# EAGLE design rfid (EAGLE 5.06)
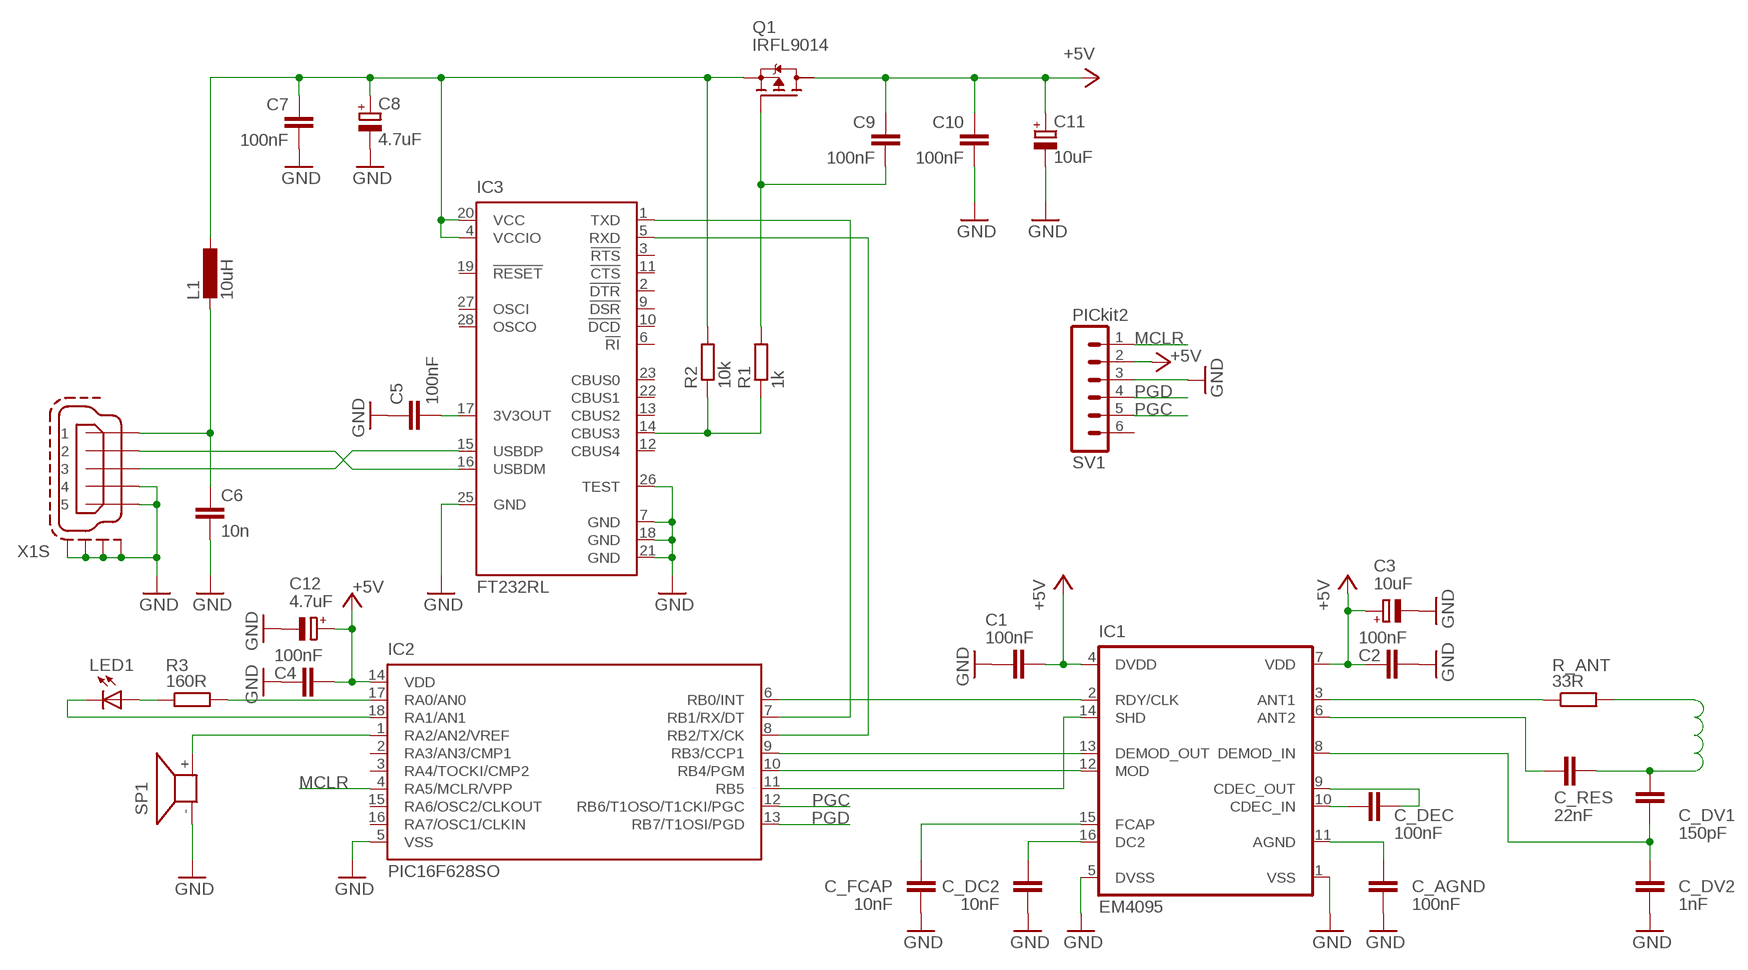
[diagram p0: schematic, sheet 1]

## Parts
C1  100nF  C-EUC1206  [C1206]
C2  100nF  C-EUC1206  [C1206]
C3  10uF  CPOL-EUB/3528-21R  [B/3528-21R]
C4  100nF  C-EUC1206  [C1206]
C5  100nF  C-EUC1206  [C1206]
C6  10n  C-EUC1206  [C1206]
C7  100nF  C-EUC1206  [C1206]
C8  4.7uF  CPOL-EUB/3528-21R  [B/3528-21R]
C9  100nF  C-EUC1206  [C1206]
C10  100nF  C-EUC1206  [C1206]
C11  10uF  CPOL-EUB/3528-21R  [B/3528-21R]
C12  4.7uF  CPOL-EUB/3528-21R  [B/3528-21R]
C_AGND  100nF  C-EUC1206  [C1206]
C_DC2  10nF  C-EUC1206  [C1206]
C_DEC  100nF  C-EUC1206  [C1206]
C_DV1  150pF  C-EUC1206  [C1206]
C_DV2  1nF  C-EUC1206  [C1206]
C_FCAP  10nF  C-EUC1206  [C1206]
C_RES  22nF  C-EUC1206  [C1206]
IC1  EM4095  [SO16]
IC2  PIC16F628SO  [SO-18W]
IC3  FT232RL  [SSOP28]
L1  10uH  L-EU0207/10  [0207/10]
LED1  LED5MM  [LED5MM]
Q1  IRFL9014  BSP170P  [SOT223]
R1  1k  R-EU_R1206  [R1206]
R2  10k  R-EU_R1206  [R1206]
R3  160R  R-EU_R1206  [R1206]
R_ANT  33R  R-EU_R1206  [R1206]
SP1  AL11P  [AL11P]
SV1  PICkit2  MA06-1  [MA06-1]
X1  MINI-USB-SCHIELD-32005-201  [32005-201]

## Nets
5V_VCC: C7.1 C8.+ IC3.4(VCCIO) IC3.20(VCC) L1.1 Q1.3(S) R2.2
+5V: C1.2 C2.1 C3.+ C4.2 C9.1 C10.1 C11.+ C12.+ IC1.4(DVDD) IC1.7(VDD) IC2.14(VDD) Q1.4(D1) SV1.2
AGND: C_AGND.1 IC1.11(AGND)
ANTENA: C_DV1.1 C_RES.1 R_ANT.2
GND: C1.1 C2.2 C3.- C4.1 C5.1 C6.2 C7.2 C8.- C10.2 C11.- C12.- C_AGND.2 C_DC2.2 C_DV2.2 C_FCAP.2 IC1.1(VSS) IC1.5(DVSS) IC2.5(VSS) IC3.7(GND) IC3.18(GND) IC3.21(GND) IC3.25(GND) IC3.26(TEST) SP1.- SV1.3 X1.4 X1.5 X1.M1(S:S1) X1.M2(S:S2) X1.M3(S:S3) X1.M4(S:S4)
MCLR: IC2.4(RA5/MCLR/VPP) SV1.1
N$1: C_DEC.2 IC1.10(CDEC_IN)
N$2: C_DEC.1 IC1.9(CDEC_OUT)
N$3: C_RES.2 IC1.6(ANT2)
N$4: C_DV1.2 C_DV2.1 IC1.8(DEMOD_IN)
N$5: IC1.3(ANT1) R_ANT.1
N$6: C_DC2.1 IC1.16(DC2)
N$7: C_FCAP.1 IC1.15(FCAP)
N$9: IC1.13(DEMOD_OUT) IC2.9(RB3/CCP1)
N$10: IC1.2(RDY/CLK) IC2.6(RB0/INT)
N$11: IC1.12(MOD) IC2.10(RB4/PGM)
N$12: IC1.14(SHD) IC2.11(RB5)
N$13: IC2.8(RB2/TX/CK) IC3.5(RXD)
N$14: IC2.7(RB1/RX/DT) IC3.1(TXD)
N$15: C5.2 IC3.17(3V3OUT)
N$16: IC3.16(USBDM) X1.2
N$17: IC3.15(USBDP) X1.3
N$18: C6.1 L1.2 X1.1
N$19: LED1.A R3.1
N$20: IC3.14(CBUS3) R1.1 R2.1
N$21: C9.2 Q1.1(G) R1.2
N$22: IC2.17(RA0/AN0) R3.2
N$23: IC2.18(RA1/AN1) LED1.K(C)
N$24: IC2.1(RA2/AN2/VREF) SP1.+
PGC: IC2.12(RB6/T1OSO/T1CKI/PGC) SV1.5
PGD: IC2.13(RB7/T1OSI/PGD) SV1.4
Unconnected: IC2.2(RA3/AN3/CMP1) IC2.3(RA4/TOCKI/CMP2) IC2.15(RA6/OSC2/CLKOUT) IC2.16(RA7/OSC1/CLKIN) IC3.2(!DTR) IC3.3(!RTS) IC3.6(!RI) IC3.9(!DSR) IC3.10(!DCD) IC3.11(!CTS) IC3.12(CBUS4) IC3.13(CBUS2) IC3.19(!RESET) IC3.22(CBUS1) IC3.23(CBUS0) IC3.27(OSCI) IC3.28(OSCO) Q1.2(D) SV1.6

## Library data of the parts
C1 C2 C4-C7 C9 C10 C_AGND C_DC2 C_DEC C_DV1 C_DV2 C_FCAP C_RES = rcl:C-EU: CAPACITOR, European symbol
C3 C8 C11 C12 = rcl:CPOL-EU: POLARIZED CAPACITOR, European symbol
IC1 = EM Microelectronic:EM4095: Read/Write analog front end for 125kHz RFID Basestation
IC2 = microchip:PIC16F62*: FLASH-Based 8-Bit CMOS Microcontroller Source: http://ww1.microchip.com/downloads/en/DeviceDoc/40300C.pdf
IC3 = ftdichip:FT232R: Source: http://www.ftdichip.com/Documents/DataSheets/DS_FT232R_v104.pdf
L1 = rcl:L-EU: INDUCTOR, European symbol
LED1 = led:LED: LED
Q1 = transistor-fet:BSP170P: SIPMOS(R) Small-Signal-Transistor P-Channel, Enhancement mode Source: http://www.infineon.com/upload/Document/BSP170P_Rev2.4.pdf
R1-R3 R_ANT = rcl:R-EU_: RESISTOR, European symbol
SP1 = buzzer:AL11P: SPEAKER
SV1 = con-lstb:MA06-1: PIN HEADER
X1 = con-cypressindustries:MINI-USB-SCHIELD-: MINI USB-B Conector Source: www.cypressindustries.com

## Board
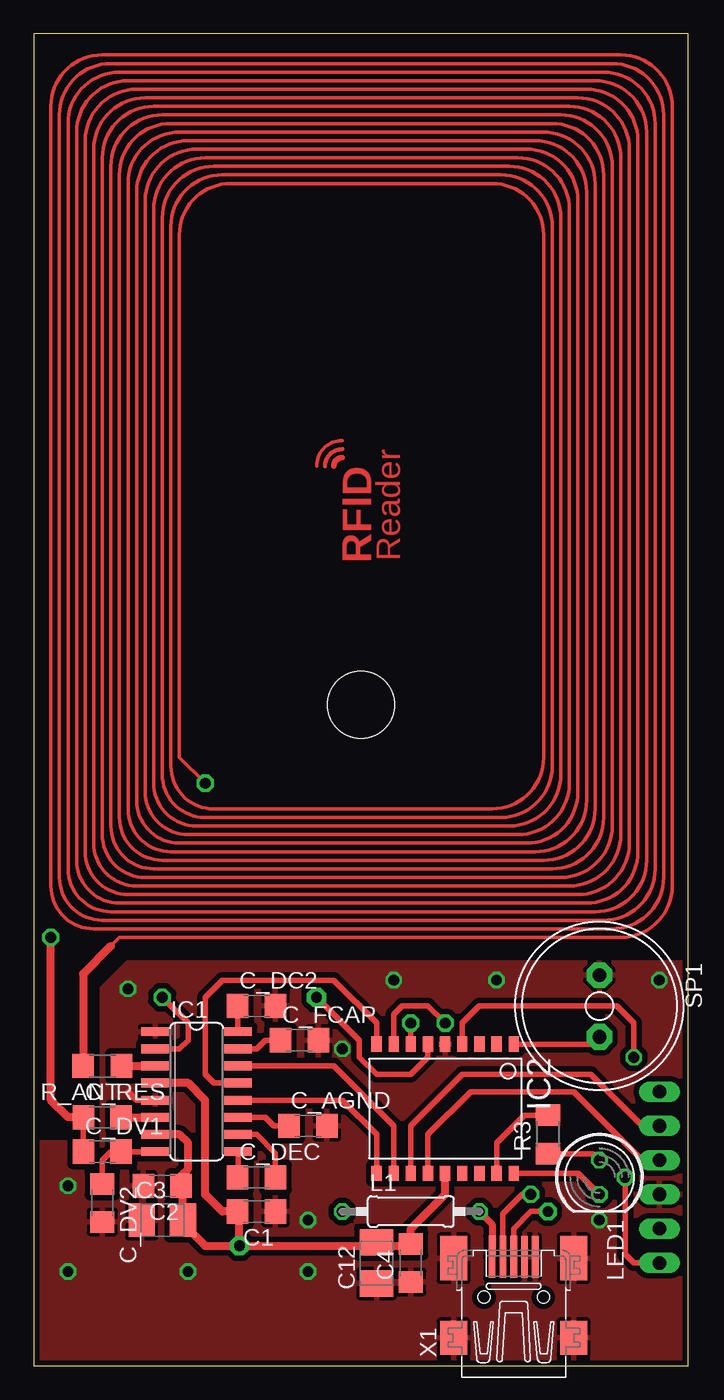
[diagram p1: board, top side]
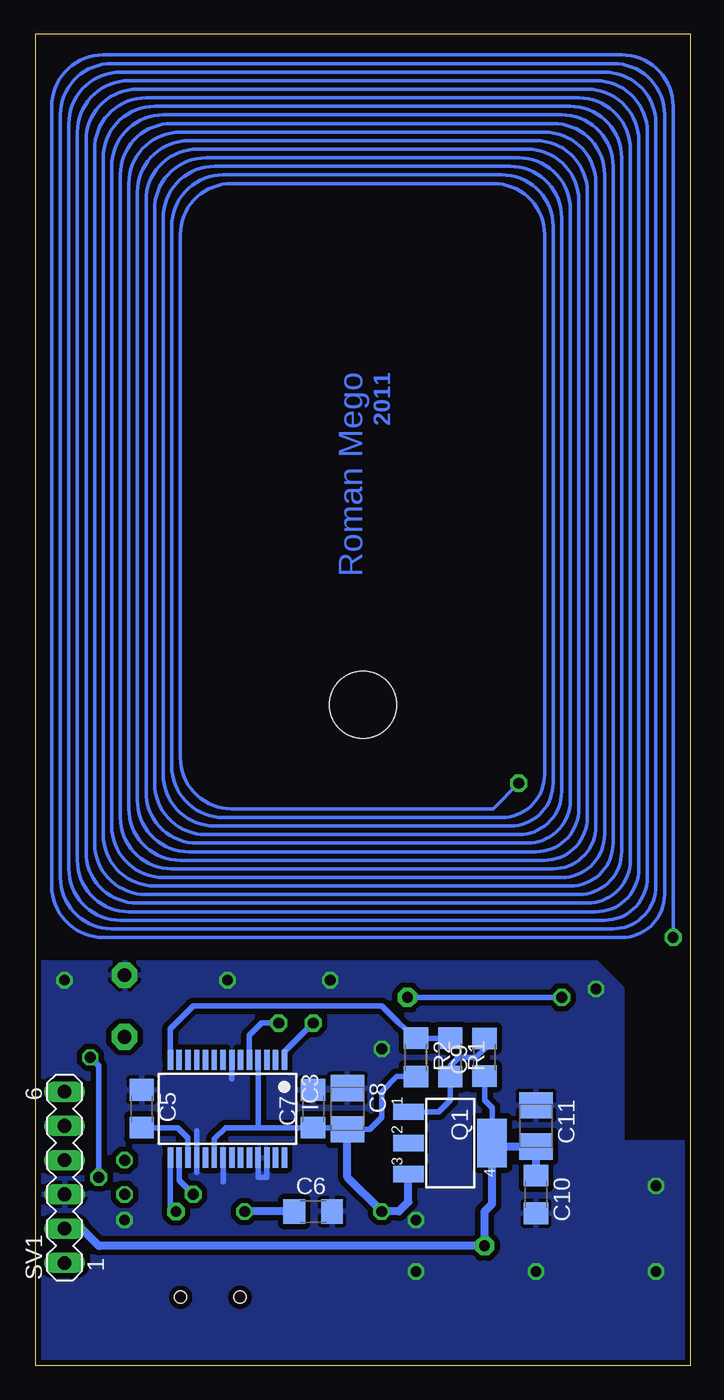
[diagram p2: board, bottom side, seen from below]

Size 48.5 x 98.73 mm. Coordinates in mm from the lower left corner, seen from the top.
Outline: 0,0 48.5,0 48.5,98.73 0,98.73 0,0
Copper layers (1*16): Top 0.0356mm / dielectric 1.5011mm / Bottom 0.0356mm
Design rules "LaenPCBOrder *": minimum track width 0.2mm, minimum drill 0.4mm, track to track 0.2mm, track to pad 0.2mm, pad to pad 0.2mm, via to via 0.2mm, smd to smd 0.2mm, copper to edge 0.4mm, drill to drill 6mil, minimum pad ring 7mil, minimum via ring 7mil, stop-mask expansion 4mil, vias tented up to drill 0mil, thermal gap 10mil
Holes 5 mm at 24.25,49

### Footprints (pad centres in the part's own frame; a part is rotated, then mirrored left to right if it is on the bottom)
C1206 = smd 1.6 x 1.8: 1 -1.4,0; 2 1.4,0
B/3528-21R = smd 1.95 x 2.5: + 1.525,0; - -1.525,0
SO16 = smd 0.66 x 2.032: 1 -4.445,-3.073; 2 -3.175,-3.073; 3 -1.905,-3.073; 4 -0.635,-3.073; 5 0.635,-3.073; 6 1.905,-3.073; 7 3.175,-3.073; 8 4.445,-3.073; 9 4.445,3.073; 10 3.175,3.073; 11 1.905,3.073; 12 0.635,3.073; 13 -0.635,3.073; 14 -1.905,3.073; 15 -3.175,3.073; 16 -4.445,3.073
SO-18W = smd 0.762 x 1.143: 1 -5.08,-4.788; 2 -3.81,-4.788; 3 -2.54,-4.788; 4 -1.27,-4.788; 5 0,-4.788; 6 1.27,-4.788; 7 2.54,-4.788; 8 3.81,-4.788; 9 5.08,-4.788; 10 5.08,4.788; 11 3.81,4.788; 12 2.54,4.788; 13 1.27,4.788; 14 0,4.788; 15 -1.27,4.788; 16 -2.54,4.788; 17 -3.81,4.788; 18 -5.08,4.788
SSOP28 = smd 0.4 x 1.5: 1 -4.225,-3.625; 2 -3.575,-3.625; 3 -2.925,-3.625; 4 -2.275,-3.625; 5 -1.625,-3.625; 6 -0.975,-3.625; 7 -0.325,-3.625; 8 0.325,-3.625; 9 0.975,-3.625; 10 1.625,-3.625; 11 2.275,-3.625; 12 2.925,-3.625; 13 3.575,-3.625; 14 4.225,-3.625; 15 4.225,3.625; 16 3.575,3.625; 17 2.925,3.625; 18 2.275,3.625; 19 1.625,3.625; 20 0.975,3.625; 21 0.325,3.625; 22 -0.325,3.625; 23 -0.975,3.625; 24 -1.625,3.625; 25 -2.275,3.625; 26 -2.925,3.625; 27 -3.575,3.625; 28 -4.225,3.625
0207/10 = drill 0.813 octagon: 1 -5.08,0; 2 5.08,0
LED5MM = drill 0.813 octagon: A -1.27,0; K 1.27,0
SOT223 = smd 1.219 x 2.235: 1 -2.311,-3.099; 2 0,-3.099; 3 2.311,-3.099 | smd 3.6 x 2.2: 4 0,3.099
R1206 = smd 1.6 x 1.803: 1 -1.422,0; 2 1.422,0
AL11P = drill 1.016 pad 1.905 octagon: + 2.286,0; - -2.286,0
MA06-1 = drill 1.016 long: 1 -6.35,0; 2 -3.81,0; 3 -1.27,0; 4 1.27,0; 5 3.81,0; 6 6.35,0
32005-201 = smd 3.1 x 0.5: 1 3,1.6; 2 3,0.8; 3 3,0; 4 3,-0.8; 5 3,-1.6 | smd 2.5 x 2: M1 -3,-4.45; M2 -3,4.45 | smd 3.3 x 2: M3 2.9,4.45; M4 2.9,-4.45 | hole 0.9: 0,2.2; 0,-2.2

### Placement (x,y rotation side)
C1  16.51,11.43 180 top
C2  9.53,13.34 180 top
C3  9.53,10.79 0 top
C4  27.94,7.62 90 top
C5  40.64,19.05 270 bottom
C6  27.94,11.43 0 bottom
C7  27.94,19.05 90 bottom
C8  25.4,19.05 270 bottom
C9  15.24,22.86 90 bottom
C10  11.43,12.7 270 bottom
C11  11.43,17.78 270 bottom
C12  25.4,7.62 90 top
C_AGND  20.32,17.78 0 top
C_DC2  16.51,26.67 0 top
C_DEC  16.51,13.97 0 top
C_DV1  5.08,15.88 0 top
C_DV2  5.08,12.06 270 top
C_FCAP  19.68,24.13 0 top
C_RES  5.08,18.41 0 top
IC1  12.06,20.32 270 top
IC2  30.48,19.05 180 top
IC3  34.29,19.05 180 bottom
L1  27.94,11.43 0 top
LED1  41.91,13.97 270 top
Q1  17.78,16.51 270 bottom
R1  17.78,22.86 270 bottom
R2  20.32,22.86 270 bottom
R3  38.1,17.14 90 top
R_ANT  5.08,22.23 180 top
SP1  41.91,26.67 270 top
SV1  46.35,13.97 90 bottom
X1  35.56,5.08 90 top

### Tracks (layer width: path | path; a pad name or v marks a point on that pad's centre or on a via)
5V_VCC
  Bottom 0.406: 32.02,17.65 C7.1 25.52,17.65 C8.+ 23.75,17.52 22.86,18.41 22.86,20.32 21.74,21.44 R2.2 | 32.02,17.65 IC3.4 | IC3.20 35.27,16.8 34.42,17.65 32.02,17.65
  Bottom 0.61: Q1.3 20.88,12.14 21.59,11.43 L1.1 25.4,13.97 C8.+
+5V  (via drill 0.8 pad 1.42)
  Top 0.61: IC1.4 11.43,20.95 12.7,19.68 12.7,12.7 13.97,11.43 C1.2 15.24,11.3 v15.24,8.89 | IC1.7 10.79,17.14 11.43,16.51 11.43,14.61 10.93,14.1 C2.1 11.05,13.21 C3.+ 11.05,10.54 12.7,8.89 v15.24,8.89 | IC2.14 30.48,12.7 27.94,10.16 C4.2 27.81,8.89 25.4,8.89 | v15.24,8.89 25.4,8.89 | 25.4,8.89 C12.+
  Bottom 0.406: Q1.4 14.68,19.13 15.24,19.68 C9.1
  Bottom 0.61: C10.1 C11.+ 14.43,16.25 Q1.4 14.68,11.99 15.24,11.43 v15.24,8.89 43.81,8.89 45.09,10.16 SV1.2
AGND
  Top 0.406: IC1.11 17.14,18.41 17.78,17.78 C_AGND.1
ANTENA  (via drill 0.8 pad 1.27)
  Top 0.254: 5.71,31.11 6.35,31.75 43.5,31.75 arc90 47.31,35.56 47.31,93.34 arc90 43.5,97.16 5.08,97.16 arc90 1.27,93.34 1.27,35.56 arc90 4.45,32.38 42.86,32.38 arc90 46.67,36.2 46.67,92.71 arc90 42.86,96.52 5.71,96.52 arc90 1.91,92.71 1.91,36.2 arc90 5.08,33.02 42.23,33.02 arc90 46.04,36.83 46.04,92.08 arc90 42.23,95.89 6.35,95.89 arc90 2.54,92.08 2.54,36.83 arc90 5.71,33.66 41.59,33.66 arc90 45.4,37.47 45.4,91.44 arc90 41.59,95.25 6.99,95.25 arc90 3.17,91.44 3.17,37.47 arc90 6.35,34.29 40.96,34.29 arc90 44.77,38.1 44.77,90.81 arc90 40.96,94.61 7.62,94.61 arc90 3.81,90.81 3.81,38.1 arc90 6.99,34.92 40.32,34.92 arc90 44.13,38.73 44.13,90.17 arc90 40.32,93.98 8.26,93.98 arc90 4.45,90.17 4.45,38.73 arc90 7.62,35.56 39.69,35.56 arc90 43.5,39.37 43.5,89.53 arc90 39.69,93.34 8.89,93.34 arc90 5.08,89.53 5.08,39.37 arc90 8.26,36.2 39.05,36.2 arc90 42.86,40.01 42.86,88.9 arc90 39.05,92.71 9.53,92.71 arc90 5.71,88.9 5.71,40.01 arc90 8.89,36.83 38.42,36.83 arc90 42.23,40.64 42.23,88.27 arc90 38.42,92.08 10.16,92.08 arc90 6.35,88.27 6.35,40.64 arc90 9.53,37.47 37.78,37.47 arc90 41.59,41.27 41.59,87.63 arc90 37.78,91.44 10.79,91.44 arc90 6.99,87.63 6.99,41.27 arc90 10.16,38.1 37.15,38.1 arc90 40.96,41.91 40.96,87 arc90 37.15,90.81 11.43,90.81 arc90 7.62,87 7.62,41.91 arc90 10.79,38.73 36.51,38.73 arc90 40.32,42.55 40.32,86.36 arc90 36.51,90.17 12.06,90.17 arc90 8.26,86.36 8.26,42.55 arc90 11.43,39.37 35.88,39.37 arc90 39.69,43.18 39.69,85.72 arc90 35.88,89.53 12.7,89.53 arc90 8.89,85.72 8.89,43.18 arc90 12.06,40.01 35.24,40.01 arc90 39.05,43.81 39.05,85.09 arc90 35.24,88.9 13.34,88.9 arc90 9.53,85.09 9.53,43.81 arc90 12.7,40.64 34.61,40.64 arc90 38.42,44.45 38.42,84.45 arc90 34.61,88.27 13.97,88.27 arc90 10.16,84.45 10.16,44.45 arc90 13.34,41.27 33.97,41.27 arc90 37.78,45.09 37.78,83.82 arc90 33.97,87.63 14.61,87.63 arc90 10.79,83.82 10.79,45.09 v12.7,43.18
  Top 0.406: C_DV1.1 C_RES.1
  Top 0.61: R_ANT.2 3.66,29.06 5.71,31.11 | v1.27,31.75 1.27,19.68 2.54,18.41 C_RES.1
  Bottom 0.254: v12.7,43.18 14.61,41.27 33.97,41.27 arc90 37.78,45.09 37.78,83.82 arc90 33.97,87.63 14.61,87.63 arc90 10.79,83.82 10.79,43.81 arc90 13.97,40.64 34.61,40.64 arc90 38.42,44.45 38.42,84.45 arc90 34.61,88.27 13.97,88.27 arc90 10.16,84.45 10.16,43.18 arc90 13.34,40.01 35.24,40.01 arc90 39.05,43.81 39.05,85.09 arc90 35.24,88.9 13.34,88.9 arc90 9.53,85.09 9.53,42.55 arc90 12.7,39.37 35.88,39.37 arc90 39.69,43.18 39.69,85.72 arc90 35.88,89.53 12.7,89.53 arc90 8.89,85.72 8.89,41.91 arc90 12.06,38.73 36.51,38.73 arc90 40.32,42.55 40.32,86.36 arc90 36.51,90.17 12.06,90.17 arc90 8.26,86.36 8.26,41.27 arc90 11.43,38.1 37.15,38.1 arc90 40.96,41.91 40.96,87 arc90 37.15,90.81 11.43,90.81 arc90 7.62,87 7.62,40.64 arc90 10.79,37.47 37.78,37.47 arc90 41.59,41.27 41.59,87.63 arc90 37.78,91.44 10.79,91.44 arc90 6.99,87.63 6.99,40.01 arc90 10.16,36.83 38.42,36.83 arc90 42.23,40.64 42.23,88.27 arc90 38.42,92.08 10.16,92.08 arc90 6.35,88.27 6.35,39.37 arc90 9.53,36.2 39.05,36.2 arc90 42.86,40.01 42.86,88.9 arc90 39.05,92.71 9.53,92.71 arc90 5.71,88.9 5.71,38.73 arc90 8.89,35.56 39.69,35.56 arc90 43.5,39.37 43.5,89.53 arc90 39.69,93.34 8.89,93.34 arc90 5.08,89.53 5.08,38.1 arc90 8.26,34.92 40.32,34.92 arc90 44.13,38.73 44.13,90.17 arc90 40.32,93.98 8.26,93.98 arc90 4.45,90.17 4.45,37.47 arc90 7.62,34.29 40.96,34.29 arc90 44.77,38.1 44.77,90.81 arc90 40.96,94.61 7.62,94.61 arc90 3.81,90.81 3.81,36.83 arc90 6.99,33.66 41.59,33.66 arc90 45.4,37.47 45.4,91.44 arc90 41.59,95.25 6.99,95.25 arc90 3.17,91.44 3.17,36.2 arc90 6.35,33.02 42.23,33.02 arc90 46.04,36.83 46.04,92.08 arc90 42.23,95.89 6.35,95.89 arc90 2.54,92.08 2.54,35.56 arc90 5.71,32.38 42.86,32.38 arc90 46.67,36.2 46.67,92.71 arc90 42.86,96.52 5.71,96.52 arc90 1.91,92.71 1.91,34.92 arc90 5.08,31.75 43.5,31.75 arc90 47.31,35.56 47.31,93.34 arc90 43.5,97.16 5.08,97.16 arc90 1.27,93.34 v1.27,31.75
GND  (via drill 0.8)
  Top 0.406: IC1.5 7.62,19.68 6.99,20.32
  Bottom 0.406: 36.56,14.34 IC3.18 36.56,17.41 | 34.62,13.64 IC3.21 | IC3.7 33.97,21.28 | IC3.26 31.36,13.97 32.02,13.97 IC3.25
  other vias: 20.32,10.79 22.86,23.5 6.99,27.94 46.35,28.57 26.67,28.57 20.32,6.99 34.29,28.57 41.91,10.79 11.43,6.99 2.54,6.99 2.54,13.34
  pour Top (isolate 0.406): 48.5,0 0,0 0,16.51 5.08,16.51 5.08,27.94 6.99,29.84 48.5,29.84
  pour Bottom (isolate 0.406): 0,0 0,16.51 5.08,16.51 5.08,27.94 6.99,29.84 48.5,29.84 48.5,0
MCLR  (via drill 0.8, 0.8 pad 1.27)
  Top 0.406: IC2.4 31.75,25.4 33.02,26.67 43.18,26.67 44.45,25.4 v44.45,22.86 | v43.81,13.97 43.81,8.26 44.45,7.62 SV1.1
  Bottom 0.406: v43.81,13.97 43.81,22.23 v44.45,22.86
N$1
  Top 0.406: IC1.10 16.51,17.14 17.91,15.74 C_DEC.2
N$2
  Top 0.406: IC1.9 15.14,14 C_DEC.1
N$3
  Top 0.61: C_RES.2 IC1.6
N$4
  Top 0.406: IC1.8 C_DV1.2 5.71,15.88 5.08,15.24 C_DV2.1
N$5
  Top 0.61: R_ANT.1 IC1.3
N$6
  Top 0.406: C_DC2.1 15.11,24.79 IC1.16
N$7
  Top 0.406: IC1.15 16.51,23.5 17.14,24.13 C_FCAP.1
N$8
  Top 0.305: 21.59,66.67 arc-90 22.86,67.94
N$9
  Top 0.406: IC1.13 13.34,20.95 12.7,21.59 12.7,27.3 13.97,28.57 22.23,28.57 25.4,25.4 IC2.9
N$10  (via drill 0.8 pad 1.27, 0.8 pad 1.42)
  Top 0.406: IC2.6 29.21,22.86 27.94,21.59 25.4,21.59 24.13,22.86 24.13,24.13 v20.95,27.3 | v9.53,27.3 11.43,25.4 11.43,24.13 10.79,23.5 IC1.2
  Bottom 0.406: v9.53,27.3 v20.95,27.3
N$11
  Top 0.406: IC1.12 22.86,19.68 25.4,17.14 IC2.10
N$12
  Top 0.406: IC1.14 22.23,22.23 26.67,17.78 IC2.11
N$13  (via drill 0.8 pad 1.27)
  Top 0.406: IC2.8 26.67,26.04 27.3,26.67 29.21,26.67 v30.48,25.4
  Bottom 0.406: IC3.5 32.66,24.48 31.75,25.4 v30.48,25.4
N$14  (via drill 0.8 pad 1.27)
  Top 0.406: v27.94,25.4 IC2.7
  Bottom 0.406: IC3.1 30.07,23.27 v27.94,25.4
N$15
  Bottom 0.406: IC3.17 37.22,16.89 37.97,17.65 C5.2
N$16  (via drill 0.8 pad 1.27)
  Top 0.406: X1.2 34.76,11.27 36.2,12.7 v36.83,12.7
  Bottom 0.406: v36.83,12.7 37.87,13.73 IC3.16
N$17  (via drill 0.8 pad 1.27)
  Top 0.406: X1.3 35.56,10.16 36.83,11.43 v38.1,11.43
  Bottom 0.406: v38.1,11.43 38.52,11.85 IC3.15
N$18
  Top 0.508: X1.1 33.96,10.49 L1.2
  Bottom 0.61: C6.1 L1.2
N$19
  Top 0.406: R3.1 41.43,15.72 LED1.A
N$20
  Bottom 0.406: IC3.14 38.52,24.98 36.83,26.67 22.86,26.67 21.59,25.4 R2.1 R1.1
N$21
  Bottom 0.406: C9.2 15.24,23.5 15.88,22.86 17.14,22.86 17.78,22.23 R1.2 17.78,19.68 18.64,18.82 Q1.1
N$22
  Top 0.406: IC2.17 34.29,16.51 36.35,18.57 R3.2
N$23
  Top 0.406: IC2.18 40.35,14.26 LED1.K
N$24
  Top 0.406: IC2.1 41.36,23.84 SP1.+
N$25
  Top 0.254: 20.95,66.67 arc-90 22.86,68.58
N$26
  Top 0.406: 22.23,66.67 arc-90 22.86,67.31
PGC
  Top 0.406: IC2.12 27.94,17.78 31.75,21.59 41.27,21.59 45.09,17.78 SV1.5
PGD
  Top 0.406: IC2.13 29.21,17.14 32.38,20.32 40.01,20.32 45.09,15.24 SV1.4

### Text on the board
Top: Reader | RFID
Bottom: 2011 | Roman Mego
